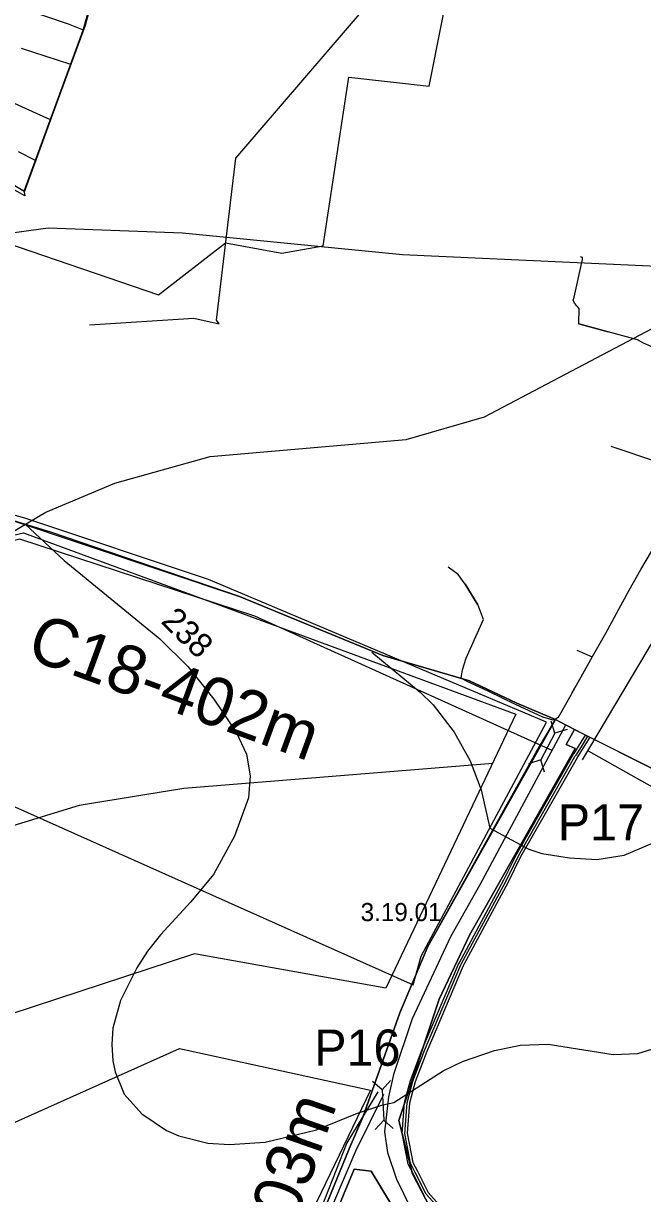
# Model space of a CAD drawing. Extents: x -662500 to -653478, y -1056827 to -1049993.
# Drawn here: x -660434.3 to -660178.1, y -1052767 to -1052282.8 of the extents above; entities that cross this region are included whole.
import ezdxf

# ---------------------------------------------------------------- set-up
doc = ezdxf.new("R2010")
doc.units = 0
for name, color, linetype in [('63LINIE', 7, 'Continuous'), ('Vrstva 1', 7, 'Continuous'), ('Vrstva 12', 7, 'Continuous'), ('Vrstva 13', 7, 'Continuous'), ('Vrstva 16', 7, 'Continuous'), ('Vrstva 18', 7, 'Continuous'), ('Vrstva 20', 7, 'Continuous'), ('Vrstva 24', 7, 'Continuous'), ('Vrstva 37', 7, 'Continuous'), ('Vrstva 42', 7, 'Continuous'), ('Vrstva 44', 7, 'Continuous'), ('Vrstva 45', 7, 'Continuous'), ('Vrstva 47', 7, 'Continuous'), ('Vrstva 48', 7, 'Continuous'), ('Vrstva 5', 7, 'Continuous'), ('Vrstva 57', 7, 'Continuous'), ('Vrstva 6', 7, 'Continuous'), ('Vrstva 61', 7, 'Continuous'), ('Vrstva 7', 7, 'Continuous')]:
    doc.layers.add(name, color=color, linetype=linetype)

msp = doc.modelspace()

# ---------------------------------------------------------------- linework, layer by layer
at = {"layer": '63LINIE'}
msp.add_lwpolyline([(-660209.97, -1052573.15), (-660245.51, -1052639.2), (-660257.59, -1052660.8), (-660273.49, -1052694.67), (-660281.15, -1052717.64), (-660283.31, -1052726.96), (-660284.88, -1052741.49), (-660283.7, -1052750.03), (-660279.97, -1052761.03), (-660274.18, -1052772.81)], dxfattribs=at)
at = {"layer": 'Vrstva 1'}
for points in [[(-660422.93, -1052493.24), (-660440.11, -1052488.01), (-660465.85, -1052493.9), (-660465.85, -1052493.64), (-660487.56, -1052498.42), (-660489.03, -1052498.8), (-660505.62, -1052498.66), (-660518.75, -1052498.54), (-660545.31, -1052498.31), (-660546.04, -1052495.02), (-660552.99, -1052463.61), (-660484.24, -1052323.36), (-660461.68, -1052336.25), (-660433.93, -1052352.12), (-660408.77, -1052283.62), (-660402.29, -1052259.33)], [(-659950.73, -1052341.07), (-659953.43, -1052371.96), (-659970.97, -1052359.28), (-659972.19, -1052361.09), (-659973.49, -1052362.01), (-659975.19, -1052363.21), (-659977.1, -1052363.82), (-659994.25, -1052353.87), (-660006.58, -1052379.92), (-660013.48, -1052394.37), (-660012.16, -1052394.95), (-660017.83, -1052403.53), (-660023.45, -1052415.35), (-660026.08, -1052420.89), (-660028.1, -1052425.15), (-660028.7, -1052426.13), (-660053.2, -1052466.49), (-660055.08, -1052469.76), (-660115.2, -1052577.95), (-660133.74, -1052611.33), (-660202.62, -1052576.83), (-660206.29, -1052574.94), (-660212.42, -1052571.79), (-660214.21, -1052570.87)], [(-660214.21, -1052570.87), (-660230.1, -1052564.08), (-660249.78, -1052554.78), (-660285.63, -1052544.31), (-660344.93, -1052519.88), (-660422.93, -1052493.24)]]:
    msp.add_lwpolyline(points, dxfattribs=at)
at = {"layer": 'Vrstva 12'}
msp.add_lwpolyline([(-660285.36, -1052725.95), (-660296.81, -1052749.13), (-660310.48, -1052781.12)], dxfattribs=at)
at = {"layer": 'Vrstva 13'}
msp.add_lwpolyline([(-660215.58, -1052583.57), (-660338.53, -1052528), (-660435.78, -1052496.22), (-660485.93, -1052508.66), (-660543.99, -1052523.06), (-660576.57, -1052533.77), (-660592.76, -1052515.74)], dxfattribs=at)
at = {"layer": 'Vrstva 20'}
msp.add_lwpolyline([(-660611.17, -1052274.32), (-660487.99, -1052312.15), (-660486.82, -1052314.01), (-660462.36, -1052329.02), (-660459.17, -1052336.8), (-660433.93, -1052352.12), (-660408.77, -1052283.62), (-660402.29, -1052259.33), (-660394.65, -1052237.63), (-660389.99, -1052217.3), (-660417.67, -1052208.59), (-660428.58, -1052243.68), (-660475.36, -1052232.69), (-660499.48, -1052225.45), (-660495.07, -1052211.29), (-660578.14, -1052190.03), (-660563.85, -1052144.19), (-660586.5, -1052144.05), (-660704.06, -1052109.9), (-660743.35, -1052235.04)], close=True, dxfattribs=at)
at = {"layer": 'Vrstva 24'}
for points in [[(-660157, -1052384), (-660277.5, -1052378.5), (-660368.5, -1052369.5), (-660424, -1052367.5), (-660486.5, -1052376), (-660524.5, -1052389), (-660555, -1052408.5), (-660605, -1052462.5), (-660630.5, -1052480.5), (-660652, -1052490), (-660666, -1052493), (-660680, -1052492), (-660697.5, -1052485), (-660718.5, -1052471), (-660848.5, -1052336), (-660875, -1052311), (-660886.5, -1052304.5), (-660903, -1052294), (-660919.5, -1052286), (-660980.5, -1052259.5)], [(-660680, -1052693), (-660668, -1052670), (-660625, -1052625), (-660559, -1052571), (-660471.5, -1052512.5), (-660425, -1052485), (-660396.5, -1052473), (-660357, -1052462), (-660276, -1052455), (-660243.5, -1052445.5), (-660138, -1052390)]]:
    msp.add_lwpolyline(points, dxfattribs=at)
at = {"layer": 'Vrstva 37'}
msp.add_lwpolyline([(-660920.61, -1052206.16), (-660810.17, -1052287.05), (-660506.62, -1052383.42), (-660536.22, -1052464.9), (-660540.27, -1052493.39), (-660540.27, -1052503.48), (-660534.66, -1052516.97), (-660434.32, -1052493.61), (-660230.57, -1052568.54), (-660284.32, -1052681.97), (-660363.46, -1052667.73), (-660573.1, -1052736.64), (-660686.93, -1052879.97)], dxfattribs=at)
msp.add_lwpolyline([(-661234.06, -1053140.82), (-660958.01, -1052955.16), (-660828.41, -1052935.32), (-660688.36, -1052892.92), (-660553.31, -1052789.11), (-660369.71, -1052706.96), (-660290.66, -1052724.21), (-660337.18, -1052820.64), (-660356.48, -1052923.15), (-660446.27, -1052991.51), (-660506.13, -1053013.32), (-660608.87, -1053013.32), (-660726.31, -1053026.56), (-660746.15, -1053043.81), (-660754.61, -1053064.64), (-660780.18, -1053120.96), (-660865.36, -1053222.79), (-660913.12, -1053274.78), (-660954.8, -1053281.43), (-660981.14, -1053263.41), (-661072.84, -1053185.46), (-661116.02, -1053160.8)], close=True, dxfattribs=at)
at = {"layer": 'Vrstva 42'}
for p, q in [((-660206.08, -1052586.11), (-660205.98, -1052585.95)), ((-660205.98, -1052585.95), (-660205.83, -1052585.69)), ((-660205.72, -1052585.52), (-660205.83, -1052585.69))]:
    msp.add_line(p, q, dxfattribs=at)
for points in [[(-660200.89, -1052577.7), (-660203.59, -1052582.07), (-660205.72, -1052585.52)], [(-660272.2, -1052758.2), (-660274.12, -1052754.42), (-660276.52, -1052742.1), (-660275.57, -1052729.39), (-660273.22, -1052720.43), (-660268.32, -1052707.77), (-660253.31, -1052672.38), (-660253.16, -1052672.02), (-660234.61, -1052637.59), (-660229.47, -1052627.17), (-660217.69, -1052606.5), (-660206.08, -1052586.11)], [(-660071.79, -1052917.29), (-660078.98, -1052908.26), (-660085.4, -1052901.23), (-660088.54, -1052898.23), (-660097.28, -1052891.36), (-660097.88, -1052890.86), (-660113.54, -1052878.01), (-660128.62, -1052862.3), (-660142.63, -1052848.21), (-660154.25, -1052838.33), (-660171.42, -1052826.63), (-660193.06, -1052813.87), (-660215.92, -1052802.12), (-660236.98, -1052791.1), (-660257.23, -1052778.77), (-660267.65, -1052767.16), (-660272.2, -1052758.2)]]:
    msp.add_lwpolyline(points, dxfattribs=at)
at = {"layer": 'Vrstva 44'}
msp.add_lwpolyline([(-659464.58, -1051504.83), (-659576.16, -1052069.59), (-659916.29, -1052550.1), (-660191.14, -1052457.81)], dxfattribs=at)
at = {"layer": 'Vrstva 45'}
for p, q in [((-660206.42, -1052396.01), (-660202.99, -1052380.49)), ((-660206.42, -1052396.01), (-660202.99, -1052380.49)), ((-660204.53, -1052407.12), (-660192.41, -1052410.44)), ((-660204.53, -1052407.12), (-660192.41, -1052410.44)), ((-660251.52, -1052514.75), (-660246.35, -1052523.36)), ((-660251.52, -1052514.75), (-660246.35, -1052523.36)), ((-660185.22, -1052519.32), (-660184.92, -1052519.51)), ((-660185.22, -1052519.32), (-660184.92, -1052519.51)), ((-660205.3, -1052542.07), (-660198.91, -1052544.88)), ((-660205.3, -1052542.07), (-660198.91, -1052544.88)), ((-660207.37, -1052559.86), (-660205.63, -1052556.79)), ((-660207.37, -1052559.86), (-660205.63, -1052556.79))]:
    msp.add_line(p, q, dxfattribs=at)
for points in [[(-660406.92, -1052407.55), (-660363.86, -1052404.75), (-660353.26, -1052407.03), (-660354.37, -1052405.55), (-660346.36, -1052338.47), (-660234.76, -1052208.31), (-660228.59, -1052182.33), (-660225.54, -1052166.06), (-660224.19, -1052158.96)], [(-660406.92, -1052407.55), (-660363.86, -1052404.75), (-660353.26, -1052407.03), (-660354.37, -1052405.55), (-660346.36, -1052338.47), (-660234.76, -1052208.31), (-660228.59, -1052182.33), (-660225.54, -1052166.06), (-660224.19, -1052158.96)], [(-660144.51, -1052430.7), (-660155.42, -1052425.37), (-660163.21, -1052421.57), (-660165.02, -1052420.62), (-660177.68, -1052415.03), (-660180.21, -1052413.72), (-660192.41, -1052410.44), (-660204.53, -1052407.12), (-660204.4, -1052400.73), (-660206.34, -1052398.5), (-660206.88, -1052397.29), (-660206.42, -1052396.01), (-660202.99, -1052380.49), (-660202.91, -1052379.62), (-660203.81, -1052379.36)], [(-660144.51, -1052430.7), (-660155.42, -1052425.37), (-660163.21, -1052421.57), (-660165.02, -1052420.62), (-660177.68, -1052415.03), (-660180.21, -1052413.72), (-660192.41, -1052410.44), (-660204.53, -1052407.12), (-660204.4, -1052400.73), (-660206.34, -1052398.5), (-660206.88, -1052397.29), (-660206.42, -1052396.01), (-660202.99, -1052380.49), (-660202.91, -1052379.62), (-660203.81, -1052379.36)], [(-660184.92, -1052519.51), (-660178.79, -1052508.71), (-660174.44, -1052501.31), (-660173.26, -1052499.37), (-660170.14, -1052494.25), (-660168.7, -1052491.45)], [(-660184.92, -1052519.51), (-660178.79, -1052508.71), (-660174.44, -1052501.31), (-660173.26, -1052499.37), (-660170.14, -1052494.25), (-660168.7, -1052491.45)], [(-660184.92, -1052519.51), (-660178.79, -1052508.71), (-660174.44, -1052501.31), (-660173.26, -1052499.37), (-660170.14, -1052494.25), (-660168.7, -1052491.45)], [(-660184.92, -1052519.51), (-660178.79, -1052508.71), (-660174.44, -1052501.31), (-660173.26, -1052499.37), (-660170.14, -1052494.25), (-660168.7, -1052491.45)], [(-660198.91, -1052544.88), (-660205.63, -1052556.79), (-660207.37, -1052559.86), (-660207.84, -1052560.71), (-660212.98, -1052570.03), (-660215.14, -1052571.04), (-660219.38, -1052569.79), (-660230.68, -1052564.53), (-660241.72, -1052559.17), (-660251.03, -1052554.9), (-660253.18, -1052553.69), (-660253.08, -1052552.73), (-660252.6, -1052550.23), (-660251.08, -1052545.44), (-660247.16, -1052536.41), (-660243.99, -1052529.43), (-660246, -1052523.88), (-660246.35, -1052523.36), (-660251.52, -1052514.75), (-660254.44, -1052510.74), (-660258.59, -1052507.75)], [(-660198.91, -1052544.88), (-660205.63, -1052556.79), (-660207.37, -1052559.86), (-660207.84, -1052560.71), (-660212.98, -1052570.03), (-660215.14, -1052571.04), (-660219.38, -1052569.79), (-660230.68, -1052564.53), (-660241.72, -1052559.17), (-660251.03, -1052554.9), (-660253.18, -1052553.69), (-660253.08, -1052552.73), (-660252.6, -1052550.23), (-660251.08, -1052545.44), (-660247.16, -1052536.41), (-660243.99, -1052529.43), (-660246, -1052523.88), (-660246.35, -1052523.36), (-660251.52, -1052514.75), (-660254.44, -1052510.74), (-660258.59, -1052507.75)], [(-660198.91, -1052544.88), (-660205.63, -1052556.79), (-660207.37, -1052559.86), (-660207.84, -1052560.71), (-660212.98, -1052570.03), (-660215.14, -1052571.04), (-660219.38, -1052569.79), (-660230.68, -1052564.53), (-660241.72, -1052559.17), (-660251.03, -1052554.9), (-660253.18, -1052553.69), (-660253.08, -1052552.73), (-660252.6, -1052550.23), (-660251.08, -1052545.44), (-660247.16, -1052536.41), (-660243.99, -1052529.43), (-660246, -1052523.88), (-660246.35, -1052523.36), (-660251.52, -1052514.75), (-660254.44, -1052510.74), (-660258.59, -1052507.75)], [(-660198.91, -1052544.88), (-660205.63, -1052556.79), (-660207.37, -1052559.86), (-660207.84, -1052560.71), (-660212.98, -1052570.03), (-660215.14, -1052571.04), (-660219.38, -1052569.79), (-660230.68, -1052564.53), (-660241.72, -1052559.17), (-660251.03, -1052554.9), (-660253.18, -1052553.69), (-660253.08, -1052552.73), (-660252.6, -1052550.23), (-660251.08, -1052545.44), (-660247.16, -1052536.41), (-660243.99, -1052529.43), (-660246, -1052523.88), (-660246.35, -1052523.36), (-660251.52, -1052514.75), (-660254.44, -1052510.74), (-660258.59, -1052507.75)], [(-660184.92, -1052519.51), (-660187.3, -1052523.83), (-660193.42, -1052535.15), (-660198.91, -1052544.88)], [(-660184.92, -1052519.51), (-660187.3, -1052523.83), (-660193.42, -1052535.15), (-660198.91, -1052544.88)], [(-660184.92, -1052519.51), (-660187.3, -1052523.83), (-660193.42, -1052535.15), (-660198.91, -1052544.88)], [(-660184.92, -1052519.51), (-660187.3, -1052523.83), (-660193.42, -1052535.15), (-660198.91, -1052544.88)]]:
    msp.add_lwpolyline(points, dxfattribs=at)
at = {"layer": 'Vrstva 47'}
for points in [[(-660269.25, -1052707.4), (-660254.23, -1052671.99), (-660254.06, -1052671.58), (-660235.5, -1052637.13), (-660230.35, -1052626.7), (-660218.56, -1052606.01), (-660206.95, -1052585.62), (-660206.84, -1052585.44), (-660206.68, -1052585.17), (-660206.46, -1052584.82), (-660201.77, -1052577.26), (-660200.89, -1052577.7), (-660199.97, -1052578.15), (-660204.76, -1052585.86), (-660204.98, -1052586.22), (-660205.12, -1052586.46), (-660205.21, -1052586.61), (-660216.82, -1052607), (-660228.59, -1052627.63), (-660233.72, -1052638.05), (-660252.26, -1052672.46), (-660252.39, -1052672.77), (-660267.39, -1052708.15), (-660272.27, -1052720.73), (-660274.58, -1052729.55), (-660275.51, -1052742.04), (-660273.16, -1052754.09), (-660271.31, -1052757.75), (-660266.82, -1052766.59), (-660256.58, -1052777.99)], [(-660268.49, -1052767.73), (-660273.09, -1052758.66), (-660275.07, -1052754.75), (-660277.53, -1052742.16), (-660276.56, -1052729.22), (-660274.18, -1052720.12), (-660269.25, -1052707.4)]]:
    msp.add_lwpolyline(points, dxfattribs=at)
at = {"layer": 'Vrstva 48'}
for points in [[(-660441.79, -1052373.47), (-660378.4, -1052395.02), (-660350.69, -1052373.56), (-660327.42, -1052377.81), (-660310.29, -1052374.81), (-660299.7, -1052304.97), (-660266.42, -1052308.69), (-660255.96, -1052255.95)], [(-660402.76, -1052261.89), (-660409.6, -1052285.62), (-660433.96, -1052352.54), (-660433.69, -1052354.11), (-660488.03, -1052323.42)], [(-660200.66, -1052583.72), (-660130.91, -1052622.91), (-660028.27, -1052427), (-660051.19, -1052417.33), (-660089.05, -1052417.84), (-660104.5, -1052443.28), (-660118.92, -1052446.11), (-660203.08, -1052587.5)], [(-660522.33, -1052569.27), (-660272.98, -1052680.64), (-660269.77, -1052668.76), (-660217.83, -1052571.93), (-660357.76, -1052512.94), (-660433.67, -1052487.46), (-660448.15, -1052483.44)]]:
    msp.add_lwpolyline(points, dxfattribs=at)
at = {"layer": 'Vrstva 5'}
for points in [[(-660402.29, -1052259.33), (-660408.77, -1052283.62), (-660433.93, -1052352.12), (-660484.24, -1052323.36), (-660515.63, -1052387.13), (-660552.99, -1052463.61), (-660546.04, -1052495.02), (-660552.69, -1052492.35), (-660575.76, -1052501.21), (-660598.28, -1052508.95), (-660621.02, -1052514.33), (-660637.54, -1052514.46), (-660650.58, -1052511.74), (-660708.39, -1052489.69), (-660725.92, -1052484.38), (-660738.96, -1052477.51), (-660752.07, -1052468), (-660823.62, -1052396.74), (-660884.87, -1052335.9), (-660895.91, -1052325.38), (-660905.47, -1052318.35), (-660915.41, -1052316.17), (-660963.02, -1052309.52)], [(-660440.11, -1052488.01), (-660344.93, -1052519.88), (-660285.63, -1052544.31), (-660249.78, -1052554.78), (-660230.1, -1052564.08), (-660214.21, -1052570.87), (-660266.98, -1052664.7), (-660278.62, -1052692.16), (-660293.9, -1052735.29), (-660299.49, -1052748.52), (-660332.61, -1052829.48)], [(-660332.61, -1052829.48), (-660299.49, -1052748.52), (-660293.9, -1052735.29), (-660278.62, -1052692.16), (-660266.98, -1052664.7), (-660222.13, -1052584.27), (-660214.21, -1052570.87), (-660206.29, -1052574.94), (-660209.8, -1052581.13), (-660205.98, -1052582.87), (-660249.69, -1052660.09), (-660262.25, -1052686.48), (-660278.97, -1052736.76), (-660273.35, -1052758.76), (-660266.1, -1052772.64)], [(-660266.1, -1052772.64), (-660273.35, -1052758.76), (-660278.97, -1052736.76), (-660262.25, -1052686.48), (-660249.69, -1052660.09), (-660205.98, -1052582.87), (-660209.8, -1052581.13), (-660206.29, -1052574.94), (-660133.74, -1052611.33)], [(-660328.41, -1052831.16), (-660297.44, -1052756.88), (-660290.42, -1052757.76), (-660278.43, -1052777.59)], [(-660278.43, -1052777.59), (-660290.42, -1052757.76), (-660297.44, -1052756.88), (-660328.41, -1052831.16)]]:
    msp.add_lwpolyline(points, dxfattribs=at)
at = {"layer": 'Vrstva 57'}
msp.add_lwpolyline([(-660240.14, -1052589.03), (-660367.97, -1052599.37), (-660411.21, -1052606.42), (-660478.88, -1052627.1), (-660527.29, -1052616.29), (-660561.13, -1052608.3), (-660596.85, -1052597.02), (-660704.94, -1052592.79), (-660768.57, -1052587.01)], dxfattribs=at)
at = {"layer": 'Vrstva 6'}
msp.add_lwpolyline([(-660462.36, -1052329.02), (-660459.17, -1052336.8), (-660433.93, -1052352.12), (-660409.6, -1052285.62), (-660402.29, -1052259.33), (-660394.65, -1052237.63), (-660389.99, -1052217.3), (-660417.67, -1052208.59), (-660421.03, -1052221.2), (-660428.58, -1052243.68), (-660452.47, -1052238.38), (-660475.36, -1052232.69), (-660499.48, -1052225.45), (-660495.07, -1052211.29), (-660578.14, -1052190.03), (-660563.85, -1052144.19), (-660586.5, -1052144.05), (-660704.06, -1052109.9), (-660743.35, -1052235.04), (-661096.01, -1052128.52), (-661110.22, -1052170.21), (-660506.09, -1052352.23), (-660487.99, -1052312.15)], close=True, dxfattribs=at)
at = {"layer": 'Vrstva 61'}
for points in [[(-660209.32, -1052574.97), (-660214.4, -1052576.52), (-660215.95, -1052571.45)], [(-660214.4, -1052576.52), (-660220.27, -1052587.55)], [(-660218.72, -1052592.63), (-660220.27, -1052587.55), (-660225.34, -1052589.1)], [(-660282.37, -1052720.14), (-660285.91, -1052724.09), (-660289.86, -1052720.55)], [(-660287.6, -1052724.84), (-660300.44, -1052745.99), (-660339.96, -1052846.46), (-660341.98, -1052864.26), (-660343.17, -1052902.02), (-660350.02, -1052925.08), (-660342.11, -1052939.74), (-660346.36, -1052973.19), (-660346.48, -1052992.69), (-660351.91, -1052997.78), (-660346.78, -1053021.38), (-660341.99, -1053043.43), (-660341.63, -1053053.82), (-660333.38, -1053060.6), (-660329.26, -1053111.63), (-660325.67, -1053113.36)], [(-660285.91, -1052724.09), (-660285.23, -1052736.57)], [(-660281.28, -1052740.11), (-660285.23, -1052736.57), (-660288.77, -1052740.52)]]:
    msp.add_lwpolyline(points, dxfattribs=at)
at = {"layer": 'Vrstva 7'}
for p, q in [((-660415.6, -1052283.1), (-660444.79, -1052273.32)), ((-660409.47, -1052285.53), (-660415.6, -1052283.1)), ((-660414.68, -1052299.7), (-660435.16, -1052293.16)), ((-660423.1, -1052322.64), (-660442.24, -1052314)), ((-660429.28, -1052339.47), (-660436.29, -1052335.96)), ((-660433.56, -1052490.01), (-660417.44, -1052505.03)), ((-660417.44, -1052505.03), (-660377.9, -1052537.48)), ((-660377.9, -1052537.48), (-660366.28, -1052548.82)), ((-660290.15, -1052542.99), (-660270.2, -1052559.45)), ((-660366.28, -1052548.82), (-660355.51, -1052562.43)), ((-660270.2, -1052559.45), (-660264.81, -1052564.69)), ((-660355.51, -1052562.43), (-660346.3, -1052576.03)), ((-660264.81, -1052564.69), (-660256.03, -1052576.03)), ((-660346.3, -1052576.03), (-660342.05, -1052585.1)), ((-660256.03, -1052576.03), (-660249.51, -1052587.94)), ((-660342.05, -1052585.1), (-660340.49, -1052594.17)), ((-660249.51, -1052587.94), (-660244.97, -1052599.84)), ((-660340.49, -1052594.17), (-660341.2, -1052603.24)), ((-660341.2, -1052603.24), (-660347.01, -1052619.11)), ((-660244.97, -1052599.84), (-660241.29, -1052615.71)), ((-660241.29, -1052615.71), (-660225.13, -1052624.5)), ((-660347.01, -1052619.11), (-660355.65, -1052634.99)), ((-660185.73, -1052626.91), (-660173.97, -1052621.95)), ((-660225.13, -1052624.5), (-660219.75, -1052626.2)), ((-660219.75, -1052626.2), (-660208.41, -1052628.04)), ((-660208.41, -1052628.04), (-660197.07, -1052628.75)), ((-660197.07, -1052628.75), (-660185.73, -1052626.91)), ((-660355.65, -1052634.99), (-660365.01, -1052646.32)), ((-660365.01, -1052646.32), (-660377.62, -1052659.93)), ((-660377.62, -1052659.93), (-660383, -1052666.73)), ((-660383, -1052666.73), (-660387.4, -1052673.53)), ((-660387.4, -1052673.53), (-660394.2, -1052687.14)), ((-660394.2, -1052687.14), (-660397.32, -1052698.47)), ((-660397.32, -1052698.47), (-660397.74, -1052705.28)), ((-660397.74, -1052705.28), (-660397.32, -1052712.08)), ((-660235.9, -1052707.12), (-660228.82, -1052705.56)), ((-660228.82, -1052705.56), (-660217.2, -1052705.13)), ((-660217.2, -1052705.13), (-660190.27, -1052709.39)), ((-660180.07, -1052708.96), (-660169.86, -1052705.84)), ((-660252.62, -1052712.36), (-660239.45, -1052707.83)), ((-660239.45, -1052707.83), (-660235.9, -1052707.12)), ((-660190.27, -1052709.39), (-660180.07, -1052708.96)), ((-660397.32, -1052712.08), (-660396.33, -1052716.61)), ((-660260.56, -1052716.19), (-660252.62, -1052712.36)), ((-660396.33, -1052716.61), (-660392.64, -1052725.82)), ((-660281.1, -1052729.25), (-660260.56, -1052716.19)), ((-660392.64, -1052725.82), (-660385.27, -1052734.04)), ((-660296.14, -1052733.74), (-660285.64, -1052730.24)), ((-660285.64, -1052730.24), (-660281.1, -1052729.25)), ((-660385.27, -1052734.04), (-660375.07, -1052740.85)), ((-660313, -1052740.56), (-660296.14, -1052733.74)), ((-660375.07, -1052740.85), (-660369.97, -1052743.11)), ((-660369.97, -1052743.11), (-660358.06, -1052746.09)), ((-660334.25, -1052745.67), (-660313, -1052740.56)), ((-660358.06, -1052746.09), (-660348.99, -1052746.66)), ((-660348.99, -1052746.66), (-660334.25, -1052745.67))]:
    msp.add_line(p, q, dxfattribs=at)

# ---------------------------------------------------------------- texts
at = {"layer": 'Vrstva 16'}
msp.add_text('C18-402m', height=20, rotation=339.8955, dxfattribs=at).set_placement((-660433.75, -1052545.18))
at = {"layer": 'Vrstva 18'}
msp.add_text('C6-503m', height=20, rotation=70.7142, dxfattribs=at).set_placement((-660340.84, -1052834.02))
at = {"layer": 'Vrstva 24'}
msp.add_text('3.19.01', height=7.5, dxfattribs=at).set_placement((-660294.78, -1052654.24))
at = {"layer": 'Vrstva 61'}
for s, p in [('P17', (-660213.22, -1052620.87)), ('P16', (-660313.99, -1052714.09))]:
    msp.add_text(s, height=15, dxfattribs=at).set_placement(p)
at = {"layer": 'Vrstva 7'}
msp.add_text('238', height=10, rotation=315.7087, dxfattribs=at).set_placement((-660377.83, -1052530.56))

doc.saveas('drawing.dxf')
